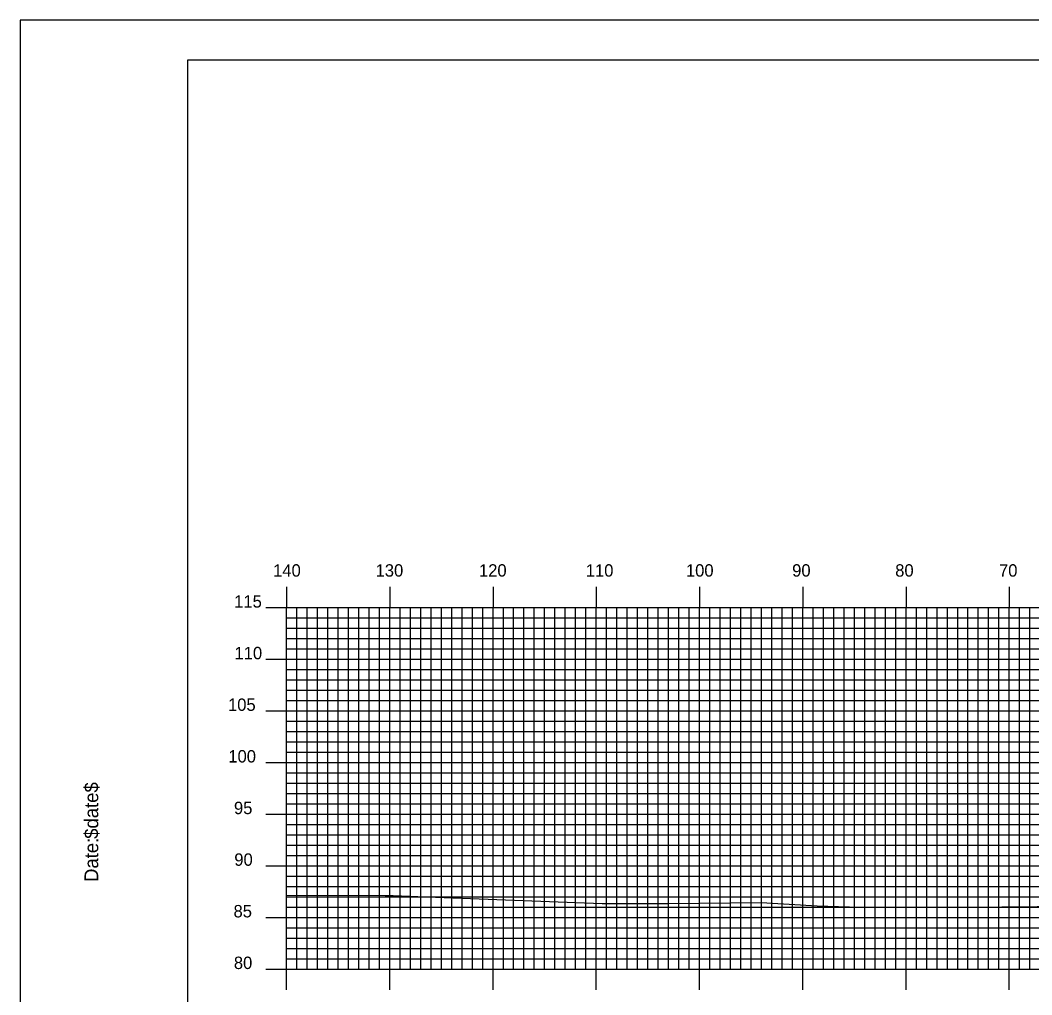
# Model space of a CAD drawing. Extents: x 1761791 to 1762134, y 442591 to 442811.
# Drawn here: x 1761791 to 1761888.9, y 442716.2 to 442810.5 of the extents above; entities that cross this region are included whole.
import ezdxf

# ---------------------------------------------------------------- set-up
doc = ezdxf.new("R2010")
doc.units = 0
for name, color, linetype in [('BORDER', 7, 'Continuous'), ('H_V ANNOTATION', 7, 'Continuous'), ('MAJOR', 7, 'Continuous'), ('MINOR', 7, 'Continuous'), ('PLOT BOUNDARY', 7, 'Continuous'), ('S_Roadway_Centerline', 7, 'Continuous')]:
    doc.layers.add(name, color=color, linetype=linetype)

msp = doc.modelspace()

# ---------------------------------------------------------------- linework, layer by layer
at = {"layer": 'BORDER'}
msp.add_lwpolyline([(1761807.153, 442596.665), (1762127.153, 442596.665), (1762127.153, 442806.665), (1761807.153, 442806.665)], close=True, dxfattribs=at)
at = {"layer": 'MAJOR'}
for p, q in [((1761816.753, 442755.669), (1761816.753, 442753.665)), ((1761826.753, 442755.669), (1761826.753, 442753.665)), ((1761836.753, 442755.669), (1761836.753, 442753.665)), ((1761846.753, 442755.669), (1761846.753, 442753.665)), ((1761856.753, 442755.669), (1761856.753, 442753.665)), ((1761866.753, 442755.669), (1761866.753, 442753.665)), ((1761876.753, 442755.669), (1761876.753, 442753.665)), ((1761886.753, 442755.669), (1761886.753, 442753.665)), ((1761814.749, 442753.665), (1761816.753, 442753.665)), ((1761816.753, 442753.665), (1762096.753, 442753.665)), ((1761816.753, 442718.665), (1761816.753, 442753.665)), ((1761816.753, 442718.665), (1761816.753, 442753.665)), ((1761816.753, 442753.665), (1762096.753, 442753.665)), ((1761826.753, 442718.665), (1761826.753, 442753.665)), ((1761836.753, 442718.665), (1761836.753, 442753.665)), ((1761846.753, 442718.665), (1761846.753, 442753.665)), ((1761856.753, 442718.665), (1761856.753, 442753.665)), ((1761866.753, 442718.665), (1761866.753, 442753.665)), ((1761876.753, 442718.665), (1761876.753, 442753.665)), ((1761886.753, 442718.665), (1761886.753, 442753.665)), ((1761814.749, 442748.665), (1761816.753, 442748.665)), ((1761816.753, 442748.665), (1762096.753, 442748.665)), ((1761814.749, 442743.665), (1761816.753, 442743.665)), ((1761816.753, 442743.665), (1762096.753, 442743.665)), ((1761814.749, 442738.665), (1761816.753, 442738.665)), ((1761816.753, 442738.665), (1762096.753, 442738.665)), ((1761814.749, 442733.665), (1761816.753, 442733.665)), ((1761816.753, 442733.665), (1762096.753, 442733.665)), ((1761814.749, 442728.665), (1761816.753, 442728.665)), ((1761816.753, 442728.665), (1762096.753, 442728.665)), ((1761814.749, 442723.665), (1761816.753, 442723.665)), ((1761816.753, 442723.665), (1762096.753, 442723.665)), ((1761814.749, 442718.665), (1761816.753, 442718.665)), ((1761816.753, 442718.665), (1762096.753, 442718.665)), ((1761816.753, 442718.665), (1762096.753, 442718.665)), ((1761816.753, 442716.661), (1761816.753, 442718.665)), ((1761826.753, 442716.661), (1761826.753, 442718.665)), ((1761836.753, 442716.661), (1761836.753, 442718.665)), ((1761846.753, 442716.661), (1761846.753, 442718.665)), ((1761856.753, 442716.661), (1761856.753, 442718.665)), ((1761866.753, 442716.661), (1761866.753, 442718.665)), ((1761876.753, 442716.661), (1761876.753, 442718.665)), ((1761886.753, 442716.661), (1761886.753, 442718.665))]:
    msp.add_line(p, q, dxfattribs=at)
at = {"layer": 'MINOR'}
for p, q in [((1761817.753, 442718.665), (1761817.753, 442753.665)), ((1761818.753, 442718.665), (1761818.753, 442753.665)), ((1761819.753, 442718.665), (1761819.753, 442753.665)), ((1761820.753, 442718.665), (1761820.753, 442753.665)), ((1761821.753, 442718.665), (1761821.753, 442753.665)), ((1761822.753, 442718.665), (1761822.753, 442753.665)), ((1761823.753, 442718.665), (1761823.753, 442753.665)), ((1761824.753, 442718.665), (1761824.753, 442753.665)), ((1761825.753, 442718.665), (1761825.753, 442753.665)), ((1761827.753, 442718.665), (1761827.753, 442753.665)), ((1761828.753, 442718.665), (1761828.753, 442753.665)), ((1761829.753, 442718.665), (1761829.753, 442753.665)), ((1761830.753, 442718.665), (1761830.753, 442753.665)), ((1761831.753, 442718.665), (1761831.753, 442753.665)), ((1761832.753, 442718.665), (1761832.753, 442753.665)), ((1761833.753, 442718.665), (1761833.753, 442753.665)), ((1761834.753, 442718.665), (1761834.753, 442753.665)), ((1761835.753, 442718.665), (1761835.753, 442753.665)), ((1761837.753, 442718.665), (1761837.753, 442753.665)), ((1761838.753, 442718.665), (1761838.753, 442753.665)), ((1761839.753, 442718.665), (1761839.753, 442753.665)), ((1761840.753, 442718.665), (1761840.753, 442753.665)), ((1761841.753, 442718.665), (1761841.753, 442753.665)), ((1761842.753, 442718.665), (1761842.753, 442753.665)), ((1761843.753, 442718.665), (1761843.753, 442753.665)), ((1761844.753, 442718.665), (1761844.753, 442753.665)), ((1761845.753, 442718.665), (1761845.753, 442753.665)), ((1761847.753, 442718.665), (1761847.753, 442753.665)), ((1761848.753, 442718.665), (1761848.753, 442753.665)), ((1761849.753, 442718.665), (1761849.753, 442753.665)), ((1761850.753, 442718.665), (1761850.753, 442753.665)), ((1761851.753, 442718.665), (1761851.753, 442753.665)), ((1761852.753, 442718.665), (1761852.753, 442753.665)), ((1761853.753, 442718.665), (1761853.753, 442753.665)), ((1761854.753, 442718.665), (1761854.753, 442753.665)), ((1761855.753, 442718.665), (1761855.753, 442753.665)), ((1761857.753, 442718.665), (1761857.753, 442753.665)), ((1761858.753, 442718.665), (1761858.753, 442753.665)), ((1761859.753, 442718.665), (1761859.753, 442753.665)), ((1761860.753, 442718.665), (1761860.753, 442753.665)), ((1761861.753, 442718.665), (1761861.753, 442753.665)), ((1761862.753, 442718.665), (1761862.753, 442753.665)), ((1761863.753, 442718.665), (1761863.753, 442753.665)), ((1761864.753, 442718.665), (1761864.753, 442753.665)), ((1761865.753, 442718.665), (1761865.753, 442753.665)), ((1761867.753, 442718.665), (1761867.753, 442753.665)), ((1761868.753, 442718.665), (1761868.753, 442753.665)), ((1761869.753, 442718.665), (1761869.753, 442753.665)), ((1761870.753, 442718.665), (1761870.753, 442753.665)), ((1761871.753, 442718.665), (1761871.753, 442753.665)), ((1761872.753, 442718.665), (1761872.753, 442753.665)), ((1761873.753, 442718.665), (1761873.753, 442753.665)), ((1761874.753, 442718.665), (1761874.753, 442753.665)), ((1761875.753, 442718.665), (1761875.753, 442753.665)), ((1761877.753, 442718.665), (1761877.753, 442753.665)), ((1761878.753, 442718.665), (1761878.753, 442753.665)), ((1761879.753, 442718.665), (1761879.753, 442753.665)), ((1761880.753, 442718.665), (1761880.753, 442753.665)), ((1761881.753, 442718.665), (1761881.753, 442753.665)), ((1761882.753, 442718.665), (1761882.753, 442753.665)), ((1761883.753, 442718.665), (1761883.753, 442753.665)), ((1761884.753, 442718.665), (1761884.753, 442753.665)), ((1761885.753, 442718.665), (1761885.753, 442753.665)), ((1761887.753, 442718.665), (1761887.753, 442753.665)), ((1761888.753, 442718.665), (1761888.753, 442753.665)), ((1761816.753, 442752.665), (1762096.753, 442752.665)), ((1761816.753, 442752.665), (1761818.757, 442752.665)), ((1761816.753, 442751.665), (1762096.753, 442751.665)), ((1761816.753, 442751.665), (1761818.757, 442751.665)), ((1761816.753, 442750.665), (1762096.753, 442750.665)), ((1761816.753, 442750.665), (1761818.757, 442750.665)), ((1761816.753, 442749.665), (1762096.753, 442749.665)), ((1761816.753, 442749.665), (1761818.757, 442749.665)), ((1761816.753, 442747.665), (1762096.753, 442747.665)), ((1761816.753, 442747.665), (1761818.757, 442747.665)), ((1761816.753, 442746.665), (1762096.753, 442746.665)), ((1761816.753, 442746.665), (1761818.757, 442746.665)), ((1761816.753, 442745.665), (1762096.753, 442745.665)), ((1761816.753, 442745.665), (1761818.757, 442745.665)), ((1761816.753, 442744.665), (1762096.753, 442744.665)), ((1761816.753, 442744.665), (1761818.757, 442744.665)), ((1761816.753, 442742.665), (1762096.753, 442742.665)), ((1761816.753, 442742.665), (1761818.757, 442742.665)), ((1761816.753, 442741.665), (1762096.753, 442741.665)), ((1761816.753, 442741.665), (1761818.757, 442741.665)), ((1761816.753, 442740.665), (1762096.753, 442740.665)), ((1761816.753, 442740.665), (1761818.757, 442740.665)), ((1761816.753, 442739.665), (1762096.753, 442739.665)), ((1761816.753, 442739.665), (1761818.757, 442739.665)), ((1761816.753, 442737.665), (1762096.753, 442737.665)), ((1761816.753, 442737.665), (1761818.757, 442737.665)), ((1761816.753, 442736.665), (1762096.753, 442736.665)), ((1761816.753, 442736.665), (1761818.757, 442736.665)), ((1761816.753, 442735.665), (1762096.753, 442735.665)), ((1761816.753, 442735.665), (1761818.757, 442735.665)), ((1761816.753, 442734.665), (1762096.753, 442734.665)), ((1761816.753, 442734.665), (1761818.757, 442734.665)), ((1761816.753, 442732.665), (1762096.753, 442732.665)), ((1761816.753, 442732.665), (1761818.757, 442732.665)), ((1761816.753, 442731.665), (1762096.753, 442731.665)), ((1761816.753, 442731.665), (1761818.757, 442731.665)), ((1761816.753, 442730.665), (1762096.753, 442730.665)), ((1761816.753, 442730.665), (1761818.757, 442730.665)), ((1761816.753, 442729.665), (1762096.753, 442729.665)), ((1761816.753, 442729.665), (1761818.757, 442729.665)), ((1761816.753, 442727.665), (1762096.753, 442727.665)), ((1761816.753, 442727.665), (1761818.757, 442727.665)), ((1761816.753, 442726.665), (1762096.753, 442726.665)), ((1761816.753, 442726.665), (1761818.757, 442726.665)), ((1761816.753, 442725.665), (1762096.753, 442725.665)), ((1761816.753, 442725.665), (1761818.757, 442725.665)), ((1761816.753, 442724.665), (1762096.753, 442724.665)), ((1761816.753, 442724.665), (1761818.757, 442724.665)), ((1761816.753, 442722.665), (1762096.753, 442722.665)), ((1761816.753, 442722.665), (1761818.757, 442722.665)), ((1761816.753, 442721.665), (1762096.753, 442721.665)), ((1761816.753, 442721.665), (1761818.757, 442721.665)), ((1761816.753, 442720.665), (1762096.753, 442720.665)), ((1761816.753, 442720.665), (1761818.757, 442720.665)), ((1761816.753, 442719.665), (1762096.753, 442719.665)), ((1761816.753, 442719.665), (1761818.757, 442719.665))]:
    msp.add_line(p, q, dxfattribs=at)
at = {"layer": 'PLOT BOUNDARY'}
msp.add_lwpolyline([(1761790.966, 442590.547), (1762130.966, 442590.547), (1762130.966, 442810.547), (1761790.966, 442810.547)], close=True, dxfattribs=at)
at = {"layer": 'S_Roadway_Centerline'}
msp.add_lwpolyline([(1761816.753, 442725.805), (1761826.304, 442725.79), (1761827.088, 442725.776), (1761829.466, 442725.691), (1761847.34, 442725.017), (1761849.654, 442725.026), (1761853.732, 442725.022), (1761862.707, 442725.114), (1761868.154, 442724.784), (1761872.296, 442724.659), (1761875.795, 442724.699), (1761882.624, 442724.644), (1761892.85, 442724.763)], dxfattribs=at)

# ---------------------------------------------------------------- texts
at = {"layer": 'BORDER'}
for s, p in [('$date$', (1761798.523, 442731.275)), ('Date:', (1761798.523, 442727.099))]:
    msp.add_text(s, height=1.3392, rotation=90, dxfattribs=at).set_placement(p)
at = {"layer": 'H_V ANNOTATION'}
for s, p in [('140', (1761815.458, 442756.665)), ('130', (1761825.383, 442756.665)), ('120', (1761835.394, 442756.665)), ('110', (1761845.736, 442756.665)), ('100', (1761855.436, 442756.665)), ('90', (1761865.725, 442756.665)), ('80', (1761875.704, 442756.665)), ('70', (1761885.757, 442756.665)), ('115', (1761811.688, 442753.665)), ('110', (1761811.72, 442748.665)), ('105', (1761811.088, 442743.665)), ('100', (1761811.12, 442738.665)), ('95', (1761811.666, 442733.665)), ('90', (1761811.698, 442728.665)), ('85', (1761811.623, 442723.665)), ('80', (1761811.655, 442718.665))]:
    msp.add_text(s, height=1.2, dxfattribs=at).set_placement(p)
at = {"layer": 'MAJOR'}
msp.add_text('-', height=0.012, dxfattribs=at).set_placement((1761816.744, 442718.665))

doc.saveas('drawing.dxf')
